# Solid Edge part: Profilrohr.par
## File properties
Username: bmolnar
Dokumentum tartalom típus: 0
Author: bmolnar
Last saved by: bmolnar
Revision: 79
Sűrűség: 0,000 kg/m^3
Pontosság: 0,990
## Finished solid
Body 1: solid body, 59 faces, 170 edges, 112 vertices.
  Faces by surface: plane 30, cylinder 29
  Edges by curve: line 112, circle 58
Bounding box of the edges (mm): 40.000 x 34.000 x 40.000, from (-20, -9.5, -20) to (20, 24.5, 20).
Cylindrical faces by radius (mm): R0.2 x12, R0.5 x12, R5 x4, R12.5 x1
Planar faces by outward normal: +x 7, +y 1, +z 7, -x 7, -y 1, -z 7
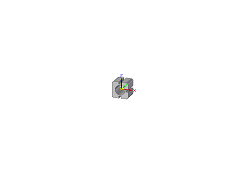
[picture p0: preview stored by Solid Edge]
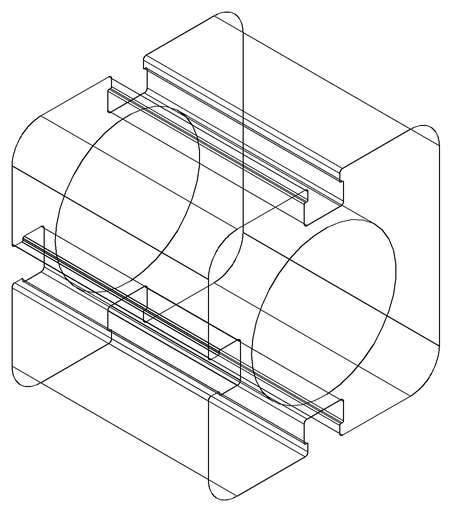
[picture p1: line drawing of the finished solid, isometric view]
